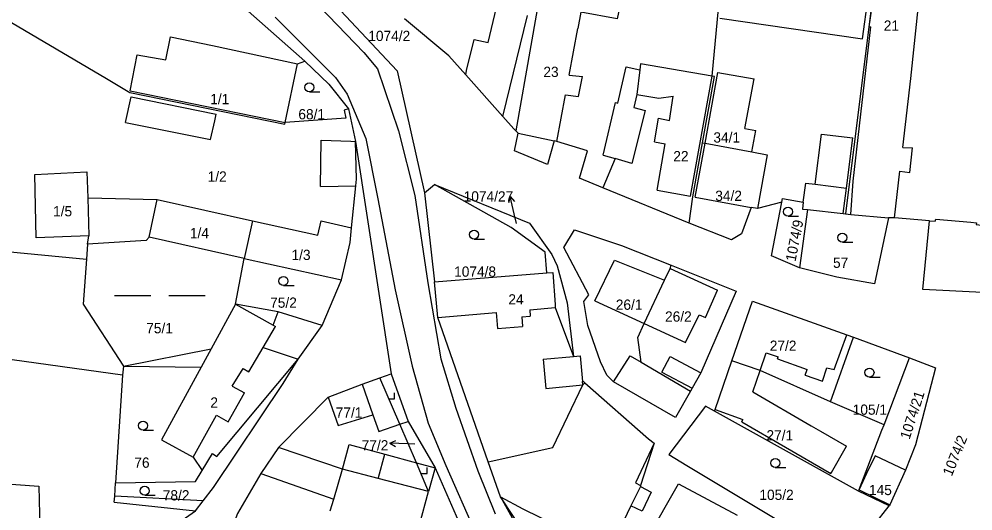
# Model space of a CAD drawing. Extents: x -746176 to -739709, y -1127410 to -1124482.
# Drawn here: x -742391.9 to -742233.7, y -1126088.1 to -1126006.4 of the extents above; entities that cross this region are included whole.
import ezdxf

# ---------------------------------------------------------------- set-up
doc = ezdxf.new("R2010")
doc.units = 0
for name, color, linetype in [('Hranice parcel', 7, 'Continuous'), ('Parcelní čísla', 7, 'Continuous'), ('Pop  PČ popisy', 7, 'Continuous'), ('Vnitřní kresba', 7, 'Continuous'), ('Značky kultur', 7, 'Continuous')]:
    doc.layers.add(name, color=color, linetype=linetype)

msp = doc.modelspace()

# ---------------------------------------------------------------- linework, layer by layer
at = {"layer": 'Hranice parcel'}
for p, q in [((-742276.95, -1126015.87), (-742275.24, -1125997.79)), ((-742249.72, -1125997.65), (-742254.82, -1126038.74)), ((-742337.26, -1126021.33), (-742336.07, -1126026.71)), ((-742336.07, -1126026.71), (-742330.17, -1126065.29)), ((-742324.67, -1126035.23), (-742323.01, -1126033.89)), ((-742280.77, -1126040.3), (-742295.06, -1126034.41)), ((-742324.67, -1126035.23), (-742323.01, -1126050.01)), ((-742265.36, -1126036.8), (-742269.44, -1126037.88)), ((-742261.12, -1126038.05), (-742262.44, -1126047.69)), ((-742353.18, -1126039.91), (-742354.56, -1126046.13)), ((-742354.56, -1126046.13), (-742370.32, -1126042.62)), ((-742356, -1126053.72), (-742354.56, -1126046.13)), ((-742354.56, -1126046.13), (-742338.41, -1126049.72)), ((-742323.01, -1126050.01), (-742304.36, -1126048.56)), ((-742341.65, -1126057.29), (-742338.41, -1126049.72)), ((-742345.58, -1126062.84), (-742341.65, -1126057.29)), ((-742257.29, -1126069.93), (-742253.51, -1126059.21)), ((-742253.51, -1126059.21), (-742244.2, -1126062.66)), ((-742248.38, -1126073.76), (-742244.2, -1126062.66)), ((-742244.2, -1126062.66), (-742239.89, -1126064.28)), ((-742374.55, -1126064.02), (-742374.74, -1126065.53)), ((-742374.55, -1126064.02), (-742361.72, -1126064.21)), ((-742374.74, -1126065.53), (-742375.89, -1126083.4)), ((-742332.05, -1126065.97), (-742330.17, -1126065.29)), ((-742248.38, -1126073.76), (-742257.29, -1126069.93)), ((-742252.65, -1126084.79), (-742276.53, -1126071.47)), ((-742252.54, -1126084.5), (-742248.77, -1126074.67)), ((-742248.77, -1126074.67), (-742248.38, -1126073.76)), ((-742314.1, -1126079.89), (-742303.39, -1126077.55)), ((-742322.88, -1126080.92), (-742323.96, -1126084.83)), ((-742312.04, -1126085.73), (-742314.1, -1126079.89)), ((-742251.31, -1126081.83), (-742252.54, -1126084.5)), ((-742244.87, -1126081.3), (-742247.47, -1126087.04)), ((-742376.03, -1126085.6), (-742375.89, -1126083.4)), ((-742361.35, -1126086.4), (-742376.03, -1126085.6)), ((-742325.49, -1126090.34), (-742323.96, -1126084.83)), ((-742247.57, -1126087.2), (-742252.65, -1126084.79)), ((-742247.47, -1126087.04), (-742247.57, -1126087.2))]:
    msp.add_line(p, q, dxfattribs=at)
for points in [[(-742380.97, -1125986.53), (-742365.73, -1125996.13), (-742363.63, -1125997.63), (-742356.74, -1126002.55), (-742344.5, -1126013.38)], [(-742302.83, -1125989.25), (-742304.53, -1125996.56), (-742309.51, -1126024.97)], [(-742349.63, -1125993.16), (-742329.2, -1126015.02), (-742324.67, -1126035.23)], [(-742394.08, -1126006.45), (-742377.42, -1126016.26), (-742373.55, -1126018.6), (-742347.83, -1126023.87), (-742347.76, -1126023.57)], [(-742309.51, -1126024.97), (-742309.85, -1126024.64), (-742311.67, -1126022.6), (-742317.81, -1126015.69), (-742320.62, -1126012.53), (-742327.99, -1126006.38)], [(-742347.76, -1126023.57), (-742345.71, -1126013.84), (-742344.5, -1126013.38)], [(-742344.5, -1126013.38), (-742340.52, -1126017.22), (-742337.26, -1126021.33)], [(-742276.95, -1126015.87), (-742288.82, -1126013.86), (-742288.94, -1126014.86), (-742289.42, -1126018.96), (-742289.94, -1126021.12), (-742288.05, -1126021.59), (-742290.26, -1126030.39), (-742293.05, -1126029.57), (-742295.06, -1126034.41)], [(-742278.52, -1126026.95), (-742276.54, -1126015.94), (-742276.95, -1126015.87)], [(-742337.26, -1126021.33), (-742337.97, -1126021.51), (-742337.68, -1126022.88), (-742347.76, -1126023.57)], [(-742295.06, -1126034.41), (-742298.95, -1126032.8), (-742297.59, -1126028.26), (-742302.72, -1126026.73), (-742303.16, -1126026.63), (-742304.27, -1126030.53), (-742309.75, -1126028.26), (-742309.14, -1126025.34), (-742309.51, -1126024.97)], [(-742336.75, -1126041.07), (-742336.05, -1126034.11), (-742335.93, -1126032.98), (-742336.07, -1126026.71)], [(-742280.77, -1126040.3), (-742280.14, -1126035.91), (-742278.52, -1126026.95)], [(-742278.52, -1126026.95), (-742278.1, -1126027.02), (-742270.33, -1126028.47), (-742267.82, -1126028.93), (-742269.44, -1126037.88)], [(-742389.08, -1126042.73), (-742389.31, -1126032.23), (-742380.68, -1126031.76), (-742380.48, -1126036.11), (-742380.34, -1126042.38), (-742389.08, -1126042.73)], [(-742304.36, -1126048.56), (-742304.63, -1126045.08), (-742310.25, -1126041.01), (-742323.01, -1126033.89)], [(-742323.01, -1126033.89), (-742307.21, -1126040.31), (-742303.55, -1126045.47), (-742302.63, -1126047.36), (-742301.01, -1126053.5), (-742299.94, -1126062.42)], [(-742370.32, -1126042.62), (-742368.99, -1126036.39), (-742353.18, -1126039.91)], [(-742265.36, -1126036.8), (-742265.25, -1126036.21), (-742261.83, -1126036.83), (-742261.97, -1126037.96), (-742261.12, -1126038.05)], [(-742269.44, -1126037.88), (-742270.44, -1126037.69), (-742272.05, -1126042.07), (-742273.73, -1126043.08), (-742280.77, -1126040.3)], [(-742262.44, -1126047.69), (-742267.12, -1126045.73), (-742265.36, -1126036.8)], [(-742261.12, -1126038.05), (-742255.21, -1126038.69), (-742254.82, -1126038.74)], [(-742247.69, -1126039.39), (-742250.03, -1126050.34), (-742256.28, -1126049.23), (-742262.44, -1126047.69)], [(-742254.82, -1126038.74), (-742253.91, -1126038.83), (-742247.69, -1126039.39)], [(-742240.91, -1126039.92), (-742246.7, -1126039.43), (-742247.69, -1126039.39)], [(-742240.91, -1126039.92), (-742239.93, -1126039.95), (-742239.83, -1126039.64), (-742234.01, -1126040.12), (-742233.11, -1126040.21), (-742233.15, -1126040.51), (-742227.7, -1126041.18), (-742227.29, -1126038.4), (-742226.7, -1126038.48)], [(-742353.18, -1126039.91), (-742342.34, -1126042.31), (-742341.81, -1126039.93), (-742336.75, -1126041.07)], [(-742338.41, -1126049.72), (-742336.99, -1126043.5), (-742336.75, -1126041.07)], [(-742293.29, -1126066.63), (-742294.4, -1126065.54), (-742295.46, -1126063.33), (-742297.55, -1126057.25), (-742298.22, -1126053.27), (-742297.41, -1126052.17), (-742301.53, -1126044.31), (-742299.77, -1126041.41), (-742291.99, -1126043.99), (-742283.72, -1126047.27)], [(-742222.2, -1126052.27), (-742242, -1126051.32), (-742240.91, -1126039.92)], [(-742370.32, -1126042.62), (-742370.8, -1126043.17), (-742380.56, -1126043.75), (-742380.73, -1126046.24)], [(-742408.01, -1126059.51), (-742408.36, -1126043.59), (-742380.73, -1126046.24)], [(-742380.73, -1126046.24), (-742381.25, -1126053.76), (-742374.55, -1126064.02)], [(-742293.29, -1126066.63), (-742290.54, -1126062.33), (-742288.73, -1126063.39), (-742289.27, -1126059.25), (-742288.22, -1126056.95), (-742284.85, -1126049.74), (-742283.92, -1126047.8), (-742283.72, -1126047.27)], [(-742283.72, -1126047.27), (-742272.96, -1126051.59), (-742278.82, -1126065.11), (-742280.26, -1126067.67), (-742280.55, -1126068.19), (-742283.01, -1126072.54), (-742293.29, -1126066.63)], [(-742304.36, -1126048.56), (-742303.36, -1126048.48), (-742302.98, -1126053.8), (-742302.95, -1126054.3), (-742299.94, -1126062.42)], [(-742314.1, -1126079.89), (-742322.45, -1126055.94), (-742323.01, -1126050.01)], [(-742356, -1126053.72), (-742360.04, -1126061.13), (-742361.72, -1126064.21)], [(-742341.65, -1126057.29), (-742348.91, -1126055.02), (-742356, -1126053.72)], [(-742273.66, -1126063.16), (-742270.23, -1126053.23), (-742254.62, -1126058.8), (-742253.51, -1126059.21)], [(-742374.74, -1126065.53), (-742395.07, -1126062.68), (-742408.01, -1126059.51)], [(-742361.52, -1126081.36), (-742359.82, -1126078.52), (-742359.07, -1126079.02), (-742345.58, -1126062.84)], [(-742361.35, -1126086.4), (-742359.63, -1126084.17), (-742348.08, -1126066.91), (-742345.58, -1126062.84)], [(-742299.94, -1126062.42), (-742298.84, -1126062.32), (-742298.44, -1126066.59)], [(-742276.53, -1126071.47), (-742276.45, -1126071.24), (-742273.66, -1126063.16)], [(-742257.29, -1126069.93), (-742268.97, -1126064.76), (-742273.66, -1126063.16)], [(-742361.72, -1126064.21), (-742368.27, -1126076.26), (-742363, -1126079.14), (-742361.52, -1126081.36)], [(-742239.89, -1126064.28), (-742243.22, -1126077.07), (-742244.87, -1126081.3)], [(-742348.85, -1126077.51), (-742340.65, -1126069.17), (-742334.99, -1126067.04), (-742332.05, -1126065.97)], [(-742323.96, -1126084.83), (-742326, -1126080.07), (-742328.74, -1126073.68), (-742332.05, -1126065.97)], [(-742330.17, -1126065.29), (-742327.34, -1126073.19), (-742322.88, -1126080.92)], [(-742303.39, -1126077.55), (-742298.39, -1126067.15), (-742298.44, -1126066.59)], [(-742298.44, -1126066.59), (-742298.26, -1126066.59), (-742298.04, -1126066.78), (-742287.48, -1126076.1), (-742286.57, -1126076.81), (-742288.8, -1126083.85), (-742288.85, -1126084.02), (-742287.04, -1126084.92), (-742288.56, -1126088.12), (-742290.4, -1126087.23), (-742294.01, -1126094.72)], [(-742276.53, -1126071.47), (-742278.03, -1126070.66), (-742284.14, -1126078.7), (-742281.13, -1126080.51)], [(-742348.85, -1126077.51), (-742351.8, -1126081.83), (-742355.65, -1126088.47), (-742358.86, -1126096.77), (-742361.21, -1126097.12), (-742360.33, -1126102.97), (-742359.44, -1126108.3), (-742350.98, -1126110.66), (-742345.56, -1126112.3), (-742332.55, -1126115.34)], [(-742323.96, -1126084.83), (-742332.33, -1126082.65), (-742338.25, -1126081.12), (-742348.85, -1126077.51)], [(-742244.87, -1126081.3), (-742249.89, -1126078.92), (-742251.31, -1126081.83)], [(-742322.88, -1126080.92), (-742314.75, -1126099.48), (-742306.74, -1126108.67), (-742296.81, -1126116.44), (-742284.71, -1126122.79), (-742278, -1126126.23), (-742271.38, -1126129.77)], [(-742281.13, -1126080.51), (-742265.95, -1126089.64), (-742257.2, -1126094.39), (-742254.21, -1126093.73), (-742250.17, -1126090.53), (-742247.57, -1126087.2)], [(-742421.29, -1126105.88), (-742421.35, -1126098.94), (-742420.61, -1126091.6), (-742427.91, -1126090.46), (-742432.7, -1126089.32), (-742431.8, -1126085.57), (-742427.02, -1126086.71), (-742416.37, -1126087.94), (-742414.61, -1126082.07), (-742388.6, -1126083.94), (-742388.43, -1126090.91), (-742379.6, -1126093.36)], [(-742375.89, -1126083.4), (-742362.61, -1126083.19), (-742361.52, -1126081.36)], [(-742287.67, -1126092.56), (-742282.53, -1126083.58), (-742272.79, -1126088.75)], [(-742312.04, -1126085.73), (-742308.34, -1126087.69), (-742294.01, -1126094.72)], [(-742312.04, -1126085.73), (-742306.45, -1126095.8), (-742299, -1126102.6), (-742295.57, -1126106.49)], [(-742294.01, -1126094.72), (-742298.22, -1126102.06), (-742305.78, -1126095.19), (-742312.04, -1126085.73)], [(-742252.65, -1126084.79), (-742252.57, -1126084.58), (-742252.54, -1126084.5)], [(-742379.6, -1126093.36), (-742370.19, -1126093.35), (-742362.62, -1126088.05), (-742361.35, -1126086.4)]]:
    msp.add_lwpolyline(points, dxfattribs=at)
at = {"layer": 'Pop  PČ popisy'}
for p, q in [((-742310.455, -1126035.846), (-742310.718, -1126036.934)), ((-742309.78, -1126038.77), (-742310.455, -1126035.846)), ((-742310.455, -1126035.846), (-742309.742, -1126036.709)), ((-742309.4, -1126040.35), (-742309.78, -1126038.77)), ((-742330.419, -1126076.805), (-742329.401, -1126076.34)), ((-742327.42, -1126076.91), (-742330.419, -1126076.805)), ((-742330.419, -1126076.805), (-742329.436, -1126077.341)), ((-742326.26, -1126076.96), (-742327.42, -1126076.91))]:
    msp.add_line(p, q, dxfattribs=at)
at = {"layer": 'Vnitřní kresba'}
for p, q in [((-742250.91, -1126007.68), (-742249.31, -1125996.84)), ((-742345.15, -1126001.12), (-742334.74, -1126011.95)), ((-742252.01, -1126009.69), (-742250.78, -1126000.65)), ((-742314.11, -1126010.3), (-742312.7, -1126004.51)), ((-742244, -1126016.27), (-742242.65, -1126003.62)), ((-742349.4, -1126006.1), (-742339.39, -1126016.09)), ((-742311.67, -1126022.6), (-742307.56, -1126005.82)), ((-742275.68, -1126006.29), (-742252.01, -1126009.69)), ((-742300.68, -1126015.71), (-742299.24, -1126007.99)), ((-742253.57, -1126033.31), (-742250.61, -1126007.72)), ((-742250.91, -1126007.68), (-742250.61, -1126007.72)), ((-742367.58, -1126013.2), (-742366.76, -1126009.36)), ((-742366.76, -1126009.36), (-742359.84, -1126010.83)), ((-742317.68, -1126014.95), (-742316.39, -1126009.79)), ((-742316.39, -1126009.79), (-742314.11, -1126010.3)), ((-742359.84, -1126010.83), (-742356.97, -1126011.42)), ((-742356.97, -1126011.42), (-742345.71, -1126013.84)), ((-742373.49, -1126018.3), (-742372.32, -1126012.36)), ((-742372.32, -1126012.36), (-742367.58, -1126013.2)), ((-742334.74, -1126011.95), (-742332.47, -1126014.68)), ((-742292.61, -1126020.36), (-742291.18, -1126014.35)), ((-742291.18, -1126014.35), (-742288.94, -1126014.86)), ((-742339.39, -1126016.09), (-742337.47, -1126018.89)), ((-742332.47, -1126014.68), (-742328.99, -1126024.95)), ((-742317.81, -1126015.69), (-742317.68, -1126014.95)), ((-742300.68, -1126015.71), (-742298.47, -1126015.93)), ((-742299.1, -1126019.25), (-742298.47, -1126015.93)), ((-742280.55, -1126035.82), (-742276.95, -1126015.87)), ((-742278.1, -1126027.02), (-742275.97, -1126015.26)), ((-742275.97, -1126015.26), (-742269.97, -1126016.35)), ((-742271.51, -1126024.59), (-742269.97, -1126016.35)), ((-742245.33, -1126027.71), (-742244, -1126016.27)), ((-742374.27, -1126023.57), (-742373.33, -1126019.33)), ((-742373.49, -1126018.3), (-742347.76, -1126023.57)), ((-742373.33, -1126019.33), (-742359.21, -1126022.18)), ((-742337.47, -1126018.89), (-742334.36, -1126026.25)), ((-742302.72, -1126026.73), (-742301.28, -1126018.98)), ((-742301.28, -1126018.98), (-742299.1, -1126019.25)), ((-742289.42, -1126018.96), (-742285.79, -1126019.55)), ((-742285.79, -1126019.55), (-742283.38, -1126019.23)), ((-742284.01, -1126023.25), (-742283.38, -1126019.23)), ((-742295.01, -1126028.99), (-742292.95, -1126020.28)), ((-742292.95, -1126020.28), (-742292.61, -1126020.36)), ((-742359.45, -1126023.28), (-742359.21, -1126022.18)), ((-742374.27, -1126023.57), (-742360.14, -1126026.43)), ((-742360.14, -1126026.43), (-742359.45, -1126023.28)), ((-742286.5, -1126026.79), (-742285.82, -1126022.85)), ((-742285.82, -1126022.85), (-742284.01, -1126023.25)), ((-742328.99, -1126024.95), (-742326.26, -1126035.72)), ((-742309.14, -1126025.34), (-742303.16, -1126026.63)), ((-742271.51, -1126024.59), (-742269.67, -1126024.93)), ((-742270.33, -1126028.47), (-742269.67, -1126024.93)), ((-742259.83, -1126033.82), (-742258.82, -1126025.53)), ((-742258.82, -1126025.53), (-742253.6, -1126026.15)), ((-742341.9, -1126034.19), (-742341.81, -1126026.49)), ((-742341.81, -1126026.49), (-742336.86, -1126026.68)), ((-742336.86, -1126026.68), (-742336.07, -1126026.71)), ((-742334.36, -1126026.25), (-742332.41, -1126036.26)), ((-742286.5, -1126026.79), (-742284.74, -1126027.11)), ((-742286.06, -1126034.83), (-742284.74, -1126027.11)), ((-742279.73, -1126036), (-742278.1, -1126027.02)), ((-742254.67, -1126034.46), (-742253.6, -1126026.15)), ((-742245.33, -1126027.71), (-742243.73, -1126027.81)), ((-742244.14, -1126031.87), (-742243.73, -1126027.81)), ((-742295.01, -1126028.99), (-742293.05, -1126029.57)), ((-742246.7, -1126039.43), (-742245.79, -1126031.64)), ((-742245.79, -1126031.64), (-742244.14, -1126031.87)), ((-742253.91, -1126038.83), (-742253.57, -1126033.31)), ((-742341.9, -1126034.19), (-742336.05, -1126034.11)), ((-742286.06, -1126034.83), (-742280.55, -1126035.82)), ((-742261.83, -1126036.83), (-742261.42, -1126033.63)), ((-742261.42, -1126033.63), (-742259.83, -1126033.82)), ((-742259.83, -1126033.82), (-742254.67, -1126034.46)), ((-742255.21, -1126038.69), (-742254.67, -1126034.46)), ((-742380.48, -1126036.11), (-742368.99, -1126036.39)), ((-742332.41, -1126036.26), (-742329.51, -1126051.35)), ((-742326.26, -1126035.72), (-742324.08, -1126050.22)), ((-742279.73, -1126036), (-742270.44, -1126037.69)), ((-742380.56, -1126043.75), (-742380.34, -1126042.38)), ((-742296.38, -1126053.19), (-742293.13, -1126046.42)), ((-742293.13, -1126046.42), (-742284.85, -1126049.74)), ((-742283.92, -1126047.8), (-742276.03, -1126051.39)), ((-742324.08, -1126050.22), (-742321.93, -1126062.83)), ((-742329.51, -1126051.35), (-742326.67, -1126064.04)), ((-742278.04, -1126055.93), (-742276.03, -1126051.39)), ((-742356, -1126053.72), (-742349.76, -1126057.21)), ((-742296.38, -1126053.19), (-742288.22, -1126056.95)), ((-742349.76, -1126057.21), (-742348.91, -1126055.02)), ((-742322.45, -1126055.94), (-742312.78, -1126055.13)), ((-742312.78, -1126055.13), (-742312.54, -1126057.76)), ((-742307.2, -1126054.66), (-742302.95, -1126054.3)), ((-742307.2, -1126054.66), (-742307.11, -1126055.73)), ((-742281.38, -1126060.08), (-742279.12, -1126055.5)), ((-742279.12, -1126055.5), (-742278.04, -1126055.93)), ((-742349.76, -1126057.21), (-742349.36, -1126057.44)), ((-742308.51, -1126055.85), (-742307.11, -1126055.73)), ((-742308.51, -1126055.85), (-742308.37, -1126057.45)), ((-742288.22, -1126056.95), (-742281.38, -1126060.08)), ((-742351.4, -1126060.92), (-742349.36, -1126057.44)), ((-742312.54, -1126057.76), (-742308.37, -1126057.45)), ((-742256.7, -1126064.58), (-742254.62, -1126058.8)), ((-742374.55, -1126064.02), (-742360.04, -1126061.13)), ((-742353.77, -1126064.97), (-742351.4, -1126060.92)), ((-742351.4, -1126060.92), (-742345.58, -1126062.84)), ((-742268.97, -1126064.76), (-742267.96, -1126061.83)), ((-742267.96, -1126061.83), (-742265.97, -1126062.48)), ((-742321.93, -1126062.83), (-742319.44, -1126070.99)), ((-742304.95, -1126062.87), (-742299.94, -1126062.42)), ((-742304.95, -1126062.87), (-742304.51, -1126067.72)), ((-742288.73, -1126063.39), (-742280.55, -1126068.19)), ((-742285.27, -1126065.04), (-742283.9, -1126062.43)), ((-742283.9, -1126062.43), (-742278.82, -1126065.11)), ((-742266.08, -1126062.81), (-742265.97, -1126062.48)), ((-742266.08, -1126062.81), (-742261.19, -1126064.58)), ((-742356.53, -1126067.33), (-742354.74, -1126064.4)), ((-742354.74, -1126064.4), (-742353.77, -1126064.97)), ((-742326.67, -1126064.04), (-742324.05, -1126073.49)), ((-742285.27, -1126065.04), (-742280.26, -1126067.67)), ((-742270.19, -1126068.29), (-742268.97, -1126064.76)), ((-742261.51, -1126065.53), (-742261.19, -1126064.58)), ((-742258.63, -1126066.51), (-742257.89, -1126064.32)), ((-742257.89, -1126064.32), (-742256.7, -1126064.58)), ((-742298.39, -1126067.15), (-742298.04, -1126066.78)), ((-742261.51, -1126065.53), (-742258.63, -1126066.51)), ((-742356.53, -1126067.33), (-742354.51, -1126068.45)), ((-742334.99, -1126067.04), (-742333.23, -1126072.08)), ((-742304.51, -1126067.72), (-742298.39, -1126067.15)), ((-742270.19, -1126068.29), (-742260.53, -1126073.92)), ((-742357.19, -1126073.27), (-742354.51, -1126068.45)), ((-742340.65, -1126069.17), (-742338.97, -1126073.9)), ((-742319.44, -1126070.99), (-742315.8, -1126081.39)), ((-742276.45, -1126071.24), (-742271.85, -1126072.87)), ((-742363, -1126079.14), (-742359.15, -1126072.18)), ((-742359.15, -1126072.18), (-742357.19, -1126073.27)), ((-742338.97, -1126073.9), (-742333.23, -1126072.08)), ((-742333.23, -1126072.08), (-742332.24, -1126074.89)), ((-742272.03, -1126073.27), (-742271.85, -1126072.87)), ((-742332.24, -1126074.89), (-742328.74, -1126073.68)), ((-742328.74, -1126073.68), (-742327.34, -1126073.19)), ((-742324.05, -1126073.49), (-742321.12, -1126080.53)), ((-742272.03, -1126073.27), (-742257.51, -1126081.69)), ((-742260.53, -1126073.92), (-742258.95, -1126074.79)), ((-742258.95, -1126074.79), (-742254.63, -1126077.29)), ((-742338.25, -1126081.12), (-742337.16, -1126077.04)), ((-742337.16, -1126077.04), (-742331.24, -1126078.64)), ((-742286.57, -1126076.81), (-742289.68, -1126083.4)), ((-742257.14, -1126081.66), (-742254.63, -1126077.29)), ((-742332.29, -1126082.49), (-742331.24, -1126078.64)), ((-742331.24, -1126078.64), (-742326, -1126080.07)), ((-742326, -1126080.07), (-742322.88, -1126080.92)), ((-742321.12, -1126080.53), (-742314.64, -1126095.13)), ((-742351.8, -1126081.83), (-742339.7, -1126086.09)), ((-742339.7, -1126086.09), (-742338.25, -1126081.12)), ((-742332.33, -1126082.65), (-742332.29, -1126082.49)), ((-742315.8, -1126081.39), (-742312.95, -1126088.54)), ((-742257.51, -1126081.69), (-742257.24, -1126081.84)), ((-742257.24, -1126081.84), (-742257.14, -1126081.66)), ((-742288.85, -1126084.02), (-742290.4, -1126087.23)), ((-742289.68, -1126083.4), (-742288.8, -1126083.85)), ((-742376.1, -1126086.6), (-742376.03, -1126085.6)), ((-742252.57, -1126084.58), (-742247.47, -1126087.04)), ((-742376.1, -1126086.6), (-742362.62, -1126088.05)), ((-742340.28, -1126088.06), (-742339.7, -1126086.09))]:
    msp.add_line(p, q, dxfattribs=at)
msp.add_lwpolyline([(-742297.32, -1125997.63), (-742291.14, -1125998.94), (-742292.67, -1126006.4), (-742298.74, -1126005.29), (-742299.24, -1126007.99)], dxfattribs=at)
at = {"layer": 'Značky kultur'}
for p, q in [((-742343.743, -1126018.51), (-742341.993, -1126018.51)), ((-742264.343, -1126039.14), (-742262.593, -1126039.14)), ((-742316.423, -1126042.93), (-742314.673, -1126042.93)), ((-742255.333, -1126043.44), (-742253.583, -1126043.44)), ((-742348.043, -1126050.65), (-742346.293, -1126050.65)), ((-742376.059, -1126052.32), (-742370.059, -1126052.32)), ((-742367.059, -1126052.32), (-742361.059, -1126052.32)), ((-742250.843, -1126065.84), (-742249.093, -1126065.84)), ((-742330.601, -1126069.46), (-742329.6, -1126069.46)), ((-742329.6, -1126069.46), (-742329.6, -1126068.46)), ((-742371.333, -1126074.64), (-742369.583, -1126074.64)), ((-742324.21, -1126081.85), (-742324.21, -1126080.85)), ((-742266.463, -1126080.85), (-742264.713, -1126080.85)), ((-742325.211, -1126081.85), (-742324.21, -1126081.85)), ((-742371.053, -1126085.46), (-742369.303, -1126085.46))]:
    msp.add_line(p, q, dxfattribs=at)
for centre in [(-742343.743, -1126017.76), (-742264.343, -1126038.39), (-742316.423, -1126042.18), (-742255.333, -1126042.69), (-742348.043, -1126049.9), (-742250.843, -1126065.09), (-742371.333, -1126073.89), (-742266.463, -1126080.1), (-742371.053, -1126084.71)]:
    msp.add_circle(centre, 0.75, dxfattribs=at)

# ---------------------------------------------------------------- texts
at = {"layer": 'Parcelní čísla'}
for s, p in [('21', (-742248.472, -1126008.35)), ('1074/2', (-742333.975, -1126010.06)), ('23', (-742304.932, -1126016.03)), ('1/1', (-742360.198, -1126020.55)), ('68/1', (-742345.571, -1126023.06)), ('34/1', (-742276.731, -1126026.91)), ('22', (-742283.382, -1126030.02)), ('1/2', (-742360.618, -1126033.4)), ('1074/27', (-742318.156, -1126036.7)), ('34/2', (-742276.421, -1126036.6)), ('1/5', (-742386.26, -1126039.16)), ('1/4', (-742363.57, -1126042.8)), ('1/3', (-742346.71, -1126046.41)), ('57', (-742256.892, -1126047.71)), ('1074/8', (-742319.735, -1126049.18)), ('75/2', (-742350.251, -1126054.33)), ('24', (-742310.742, -1126053.79)), ('26/1', (-742292.921, -1126054.67)), ('26/2', (-742284.751, -1126056.64)), ('75/1', (-742370.811, -1126058.57)), ('27/2', (-742267.381, -1126061.48)), ('2', (-742360.17, -1126070.91)), ('77/1', (-742339.381, -1126072.57)), ('105/1', (-742253.623, -1126072.09)), ('27/1', (-742267.931, -1126076.35)), ('77/2', (-742335.071, -1126078.01)), ('76', (-742372.782, -1126080.89)), ('145', (-742250.924, -1126085.43)), ('78/2', (-742368.06, -1126086.31)), ('105/2', (-742269.103, -1126086.23))]:
    msp.add_text(s, height=1.7, dxfattribs=at).set_placement(p)
for s, rotation, p in [('1074/9', 79, (-742263.116, -1126046.757)), ('1074/21', 72, (-742244.207, -1126076.302)), ('1074/2', 68, (-742237.19, -1126082.403))]:
    msp.add_text(s, height=1.7, rotation=rotation, dxfattribs=at).set_placement(p)

doc.saveas('drawing.dxf')
